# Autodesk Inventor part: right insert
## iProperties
Author: Rich
Shininess: 20.0
PropertySet Name: _Private Model Information
Created: 2001-04
Part Number: right insert
Document SubType Name: Modeling
Designer: Rich
Control State: 0
Master: False
Checked Out: False
PropertySet Name: Design Tracking Control
Density: 0.0
Volumn: 0.0
Area: 0.0
PropertySet Name: Model Information
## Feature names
1. Derived Body1 [Tagging]
